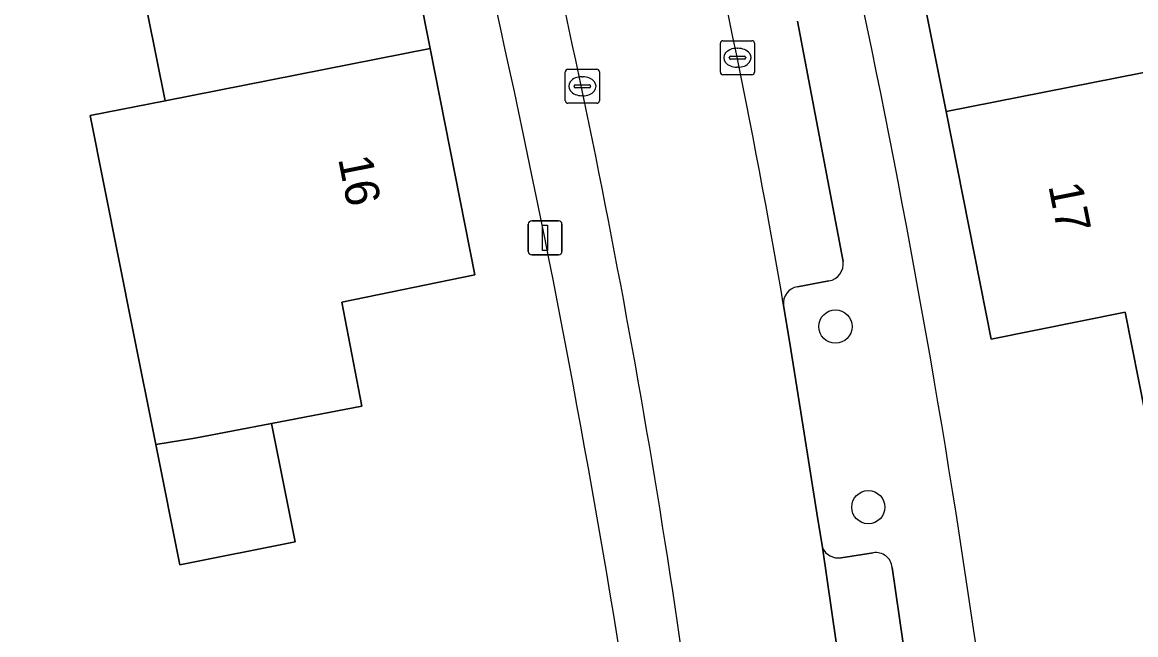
# Model space of a CAD drawing. Extents: x 159053 to 160042, y 380449 to 381423.
# Drawn here: x 159464.29 to 159497.02, y 380901.12 to 380919.13 of the extents above; entities that cross this region are included whole.
import ezdxf

# ---------------------------------------------------------------- set-up
doc = ezdxf.new("R2010")
doc.units = 0
for name, color, linetype in [('IMGEO_Boom', 7, 'Continuous'), ('IMGEO_Erf', 7, 'Continuous'), ('IMGEO_Kolk', 7, 'Continuous'), ('IMGEO_Lichtmast', 7, 'Continuous'), ('IMGEO_Pand', 7, 'Continuous'), ('IMGEO_Pand_nummerreeks', 7, 'Continuous'), ('IMGEO_Parkeervlak_open', 7, 'Continuous'), ('IMGEO_Rijbaan_lokaal_open', 7, 'Continuous'), ('IMGEO_Voetpad_open', 7, 'Continuous')]:
    doc.layers.add(name, color=color, linetype=linetype)

msp = doc.modelspace()

# ---------------------------------------------------------------- linework, layer by layer
at = {"layer": 'IMGEO_Boom'}
for centre in [(159488.191, 380910.182), (159489.157, 380904.873)]:
    msp.add_circle(centre, 0.489, dxfattribs=at)
at = {"layer": 'IMGEO_Erf'}
for points in [[(159474.954, 380925.019), (159476.275, 380918.352), (159477.591, 380911.706), (159473.681, 380910.9), (159474.269, 380907.843), (159471.62, 380907.336), (159472.316, 380903.852), (159468.925, 380903.174), (159468.218, 380906.712), (159467.543, 380910.09), (159466.285, 380916.388), (159468.488, 380916.821), (159467.213, 380923.198)], [(159498.07, 380924.515), (159499.34, 380918.065), (159500, 380914.713), (159500.584, 380911.746), (159505.503, 380912.747), (159506.185, 380909.395), (159502.201, 380908.584), (159500, 380908.136), (159497.301, 380907.587), (159496.703, 380910.605), (159492.772, 380909.815), (159491.441, 380916.505), (159490.164, 380922.924)]]:
    msp.add_lwpolyline(points, dxfattribs=at)
for centre, radius, start, end in [((159206.417, 380859.851), 288.822, 6.70726, 15.08666), ((159160.823, 380848.813), 325.18, 7.81295, 14.88202)]:
    msp.add_arc(centre, radius, start, end, dxfattribs=at)
at = {"layer": 'IMGEO_Kolk'}
for p, q in [((159484.81, 380917.657), (159484.81, 380918.509)), ((159484.885, 380918.583), (159485.737, 380918.583)), ((159485.298, 380918.363), (159485.323, 380918.363)), ((159485.811, 380918.509), (159485.811, 380917.657)), ((159485.069, 380918.077), (159485.069, 380918.089)), ((159485.507, 380918.04), (159485.109, 380918.04)), ((159485.112, 380918.126), (159485.51, 380918.126)), ((159485.553, 380918.089), (159485.553, 380918.077)), ((159480.252, 380916.821), (159480.252, 380917.673)), ((159480.327, 380917.747), (159481.179, 380917.747)), ((159481.253, 380917.673), (159481.253, 380916.821)), ((159485.321, 380917.803), (159485.296, 380917.803)), ((159480.74, 380917.527), (159480.765, 380917.527)), ((159485.737, 380917.583), (159484.885, 380917.583)), ((159480.511, 380917.241), (159480.511, 380917.253)), ((159480.949, 380917.204), (159480.551, 380917.204)), ((159480.554, 380917.29), (159480.952, 380917.29)), ((159480.995, 380917.253), (159480.995, 380917.241)), ((159481.179, 380916.747), (159480.327, 380916.747)), ((159480.763, 380916.967), (159480.738, 380916.967))]:
    msp.add_line(p, q, dxfattribs=at)
for points in [[(159484.81, 380917.657), (159484.81, 380918.509)], [(159484.885, 380918.583), (159485.737, 380918.583)], [(159485.811, 380918.509), (159485.811, 380917.657)], [(159480.252, 380916.821), (159480.252, 380917.673)], [(159480.327, 380917.747), (159481.179, 380917.747)], [(159481.253, 380917.673), (159481.253, 380916.821)], [(159485.737, 380917.583), (159484.885, 380917.583)], [(159481.179, 380916.747), (159480.327, 380916.747)]]:
    msp.add_lwpolyline(points, dxfattribs=at)
for centre, radius, start, end in [((159484.887, 380918.507), 0.0765, 91.552, 178.448), ((159484.887, 380918.507), 0.0765, 91.552, 178.448), ((159485.735, 380918.507), 0.0765, 1.552, 88.448), ((159485.735, 380918.507), 0.0765, 1.552, 88.448), ((159485.109, 380918.086), 0.0403, 85.8775, 175.7526), ((159485.106, 380918.076), 0.0366, 178.938, 274.7102), ((159485.51, 380918.083), 0.043, 264.8664, 352.4533), ((159485.514, 380918.088), 0.0386, 1.7309, 96.639), ((159480.329, 380917.671), 0.0765, 91.552, 178.448), ((159480.329, 380917.671), 0.0765, 91.552, 178.448), ((159481.177, 380917.671), 0.0765, 1.552, 88.448), ((159481.177, 380917.671), 0.0765, 1.552, 88.448), ((159484.887, 380917.659), 0.0765, 181.552, 268.448), ((159484.887, 380917.659), 0.0765, 181.552, 268.448), ((159485.735, 380917.659), 0.0765, 271.552, 358.448), ((159485.735, 380917.659), 0.0765, 271.552, 358.448), ((159480.551, 380917.25), 0.0403, 85.8775, 175.7526), ((159480.548, 380917.24), 0.0366, 178.938, 274.7102), ((159480.952, 380917.247), 0.043, 264.8664, 352.4533), ((159480.956, 380917.252), 0.0386, 1.7309, 96.639), ((159480.329, 380916.823), 0.0765, 181.552, 268.448), ((159480.329, 380916.823), 0.0765, 181.552, 268.448), ((159481.177, 380916.823), 0.0765, 271.552, 358.448), ((159481.177, 380916.823), 0.0765, 271.552, 358.448)]:
    msp.add_arc(centre, radius, start, end, dxfattribs=at)
for centre, major_axis, ratio, start_param, end_param in [((159485.297, 380918.083), (-0.387, 0.002), 0.722429, 4.712389, 7.853982), ((159485.322, 380918.083), (-0.39, 0.002), 0.717154, 1.570796, 4.712389), ((159480.739, 380917.247), (-0.387, 0.002), 0.722429, 4.712389, 7.853982), ((159480.764, 380917.247), (-0.39, 0.002), 0.717154, 1.570796, 4.712389)]:
    msp.add_ellipse(centre, major_axis=major_axis, ratio=ratio, start_param=start_param, end_param=end_param, dxfattribs=at)
at = {"layer": 'IMGEO_Lichtmast'}
for p, q in [((159479.163, 380912.389), (159479.163, 380913.189)), ((159479.163, 380913.189), (159479.163, 380912.389)), ((159479.263, 380913.289), (159480.053, 380913.289)), ((159480.053, 380913.289), (159479.263, 380913.289)), ((159480.153, 380913.189), (159480.153, 380912.389)), ((159480.153, 380912.389), (159480.153, 380913.189)), ((159480.053, 380912.289), (159479.263, 380912.289)), ((159479.263, 380912.289), (159480.053, 380912.289))]:
    msp.add_line(p, q, dxfattribs=at)
msp.add_lwpolyline([(159479.583, 380913.164), (159479.733, 380913.164), (159479.733, 380912.414), (159479.583, 380912.414), (159479.583, 380913.164)], dxfattribs=at)
for centre, start, end in [((159479.263, 380913.189), 90, 180), ((159479.263, 380913.189), 90, 180), ((159480.053, 380913.189), 0, 90), ((159480.053, 380913.189), 360, 90), ((159479.263, 380912.389), 180, 270), ((159479.263, 380912.389), 180, 270), ((159480.053, 380912.389), 270, 0), ((159480.053, 380912.389), 270, 0)]:
    msp.add_arc(centre, 0.1, start, end, dxfattribs=at)
at = {"layer": 'IMGEO_Pand'}
for points in [[(159468.488, 380916.821), (159476.275, 380918.352), (159474.954, 380925.019), (159471.031, 380924.242), (159470.261, 380927.385), (159464.292, 380925.866), (159465.072, 380922.765), (159467.213, 380923.198)], [(159499.34, 380918.065), (159498.07, 380924.515), (159490.164, 380922.924), (159491.441, 380916.505)], [(159476.275, 380918.352), (159468.488, 380916.821), (159466.285, 380916.388), (159467.543, 380910.09), (159468.218, 380906.712), (159469.359, 380906.904), (159471.62, 380907.336), (159474.269, 380907.843), (159473.681, 380910.9), (159477.591, 380911.706)], [(159499.34, 380918.065), (159491.441, 380916.505), (159492.772, 380909.815), (159496.703, 380910.605), (159497.301, 380907.587), (159500, 380908.136), (159502.201, 380908.584), (159506.185, 380909.395), (159505.503, 380912.747), (159500.584, 380911.746), (159500, 380914.713)], [(159471.62, 380907.336), (159469.359, 380906.904), (159468.218, 380906.712), (159468.925, 380903.174), (159472.316, 380903.852)]]:
    msp.add_lwpolyline(points, close=True, dxfattribs=at)
at = {"layer": 'IMGEO_Parkeervlak_open'}
for points in [[(159488.419, 380912.095), (159487.071, 380919.159)], [(159487.073, 380911.353), (159488.001, 380911.523)], [(159487.807, 380903.688), (159489.547, 380891.673)], [(159489.3, 380903.531), (159488.358, 380903.386)], [(159491.355, 380892.74), (159489.857, 380903.102)]]:
    msp.add_lwpolyline(points, dxfattribs=at)
for centre, radius, start, end in [((159264.406, 380873.012), 225.45, 9.6502, 13.72999), ((159487.905, 380912.032), 0.518, 280.6535, 7.0301), ((159487.151, 380910.869), 0.49, 99.1631, 187.4996), ((159488.278, 380903.894), 0.514, 203.5973, 278.9489), ((159489.382, 380903.061), 0.477, 4.8863, 99.907)]:
    msp.add_arc(centre, radius, start, end, dxfattribs=at)
at = {"layer": 'IMGEO_Rijbaan_lokaal_open'}
msp.add_lwpolyline([(159484.689, 380892.895), (159485.065, 380890.008), (159489.681, 380890.613), (159489.547, 380891.673), (159487.807, 380903.688), (159487.643, 380904.696), (159487.238, 380907.231), (159486.841, 380909.753), (159486.665, 380910.805)], dxfattribs=at)
for centre, radius, start, end in [((159264.406, 380873.012), 225.45, 9.6502, 13.72999), ((159216.691, 380861.712), 269.806, 6.63675, 13.16689)]:
    msp.add_arc(centre, radius, start, end, dxfattribs=at)
at = {"layer": 'IMGEO_Voetpad_open'}
for points in [[(159487.071, 380919.159), (159488.419, 380912.095)], [(159488.001, 380911.523), (159487.073, 380911.353)], [(159486.665, 380910.805), (159486.841, 380909.753), (159487.238, 380907.231), (159487.643, 380904.696), (159487.807, 380903.688)], [(159488.358, 380903.386), (159489.3, 380903.531)], [(159489.857, 380903.102), (159491.355, 380892.74)]]:
    msp.add_lwpolyline(points, dxfattribs=at)
for centre, radius, start, end in [((159206.417, 380859.851), 288.822, 6.70726, 15.08666), ((159160.823, 380848.813), 325.18, 7.81295, 14.88202), ((159216.691, 380861.712), 269.806, 6.63675, 13.16689), ((159487.905, 380912.032), 0.518, 280.6535, 7.0301), ((159487.151, 380910.869), 0.49, 99.1631, 187.4996), ((159488.278, 380903.894), 0.514, 203.5973, 278.9489), ((159489.382, 380903.061), 0.477, 4.8863, 99.907)]:
    msp.add_arc(centre, radius, start, end, dxfattribs=at)

# ---------------------------------------------------------------- texts
at = {"layer": 'IMGEO_Pand_nummerreeks'}
for s, rotation, p in [('16', 281.2011, (159473.572, 380915.118)), ('17', 281.2525, (159494.444, 380914.323))]:
    msp.add_text(s, height=1, rotation=rotation, dxfattribs=at).set_placement(p)

doc.saveas('drawing.dxf')
